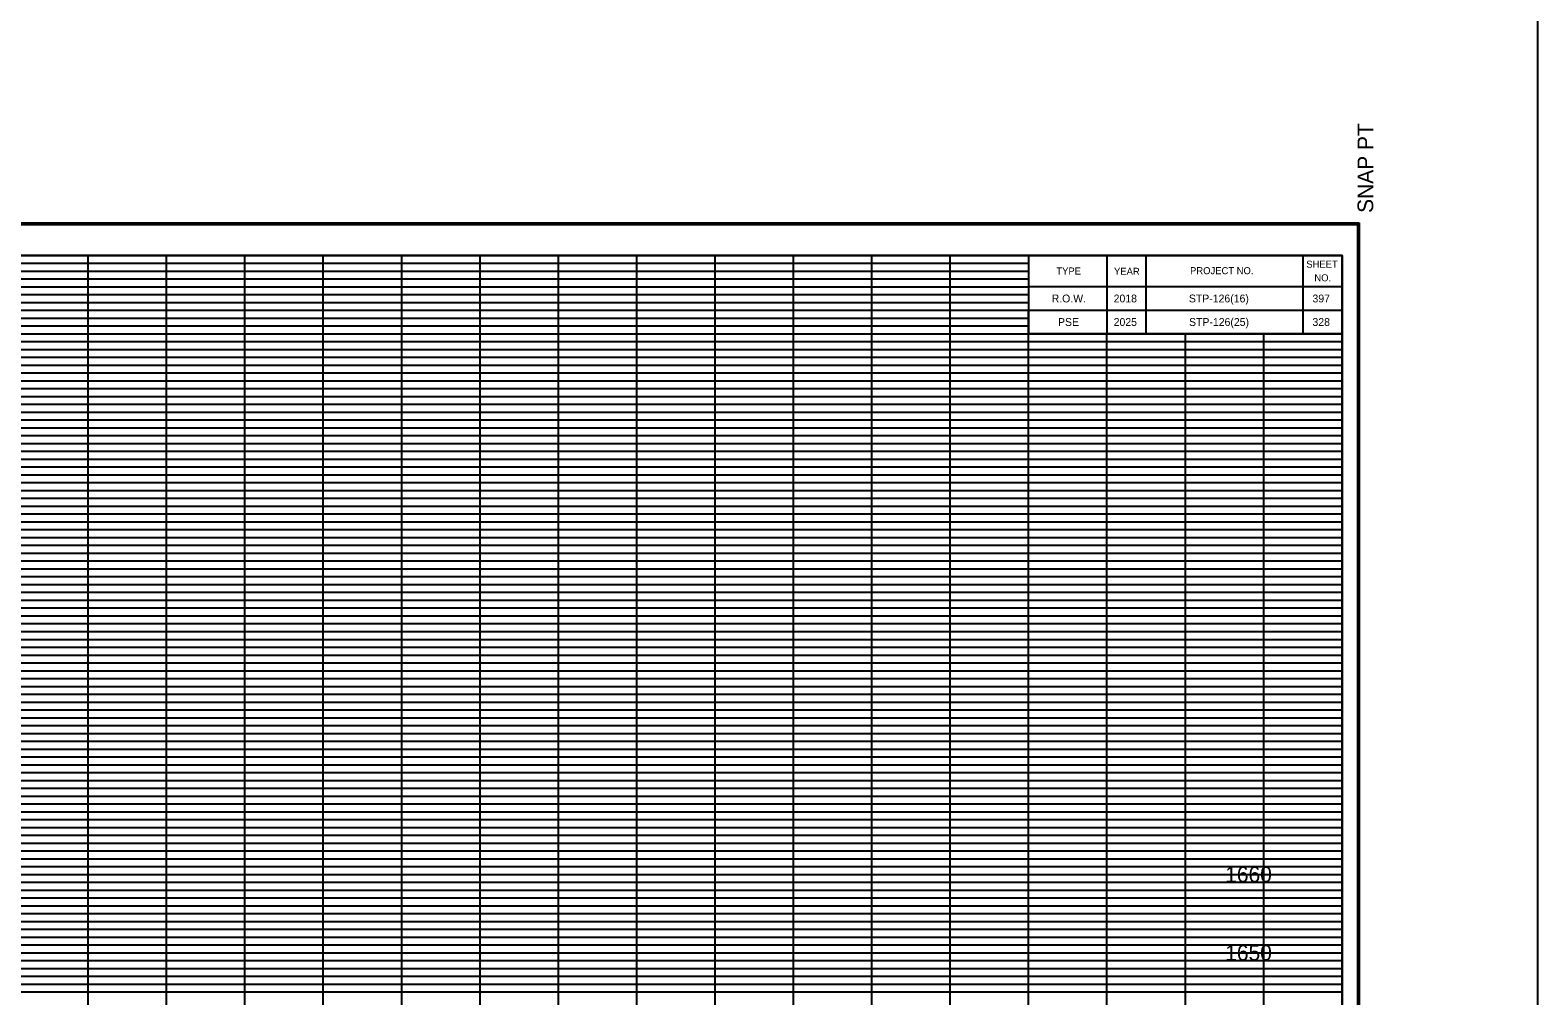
# Model space of a CAD drawing. Extents: x 955 to 1375, y 1248 to 3657.
# Drawn here: x 1152.6 to 1345, y 2735.5 to 2858.7 of the extents above; entities that cross this region are included whole.
import ezdxf

# ---------------------------------------------------------------- set-up
doc = ezdxf.new("R2010")
doc.units = 0
for name, color, linetype in [('DESIGN - SCRATCH - User 1', 7, 'Continuous'), ('DESIGN - SHEET - Corner Text', 7, 'Continuous'), ('DESIGN - SHEET - Light Grid', 7, 'Continuous'), ('DESIGN - SHEET - Linework', 7, 'Continuous'), ('DESIGN - SHEET - Plot Shape', 7, 'Continuous'), ('DESIGN - TYPICAL - Text', 7, 'Continuous'), ('DESIGN - UTILITIES - Cable (Overhead) with Text', 7, 'Continuous'), ('SURVEY - NON-TRANSPORTATION - Features Text', 7, 'Continuous')]:
    doc.layers.add(name, color=color, linetype=linetype)

# ---------------------------------------------------------------- blocks, each defined once
blk = doc.blocks.new('XSTSHT')
at = {"layer": 'DESIGN - SCRATCH - User 1'}
for p, q in [((28.5, 20.45), (28.5, 20.45)), ((29.24, 20.45), (29.24, 20.45)), ((30.49, 20.45), (30.49, 20.45)), ((31.74, 20.45), (31.74, 20.45)), ((28.5, 20.15), (28.5, 20.15)), ((29.24, 20.15), (29.24, 20.15)), ((30.49, 20.15), (30.49, 20.15)), ((31.74, 20.15), (31.74, 20.15))]:
    blk.add_line(p, q, dxfattribs=at)
at = {"layer": 'DESIGN - SHEET - Light Grid'}
for p, q in [((8, 20.9), (16, 20.9)), ((8, 20.8), (16, 20.8)), ((16, 20.9), (24, 20.9)), ((16, 20.8), (24, 20.8)), ((24, 20.9), (28, 20.9)), ((24, 20.8), (28, 20.8)), ((8, 20.7), (16, 20.7)), ((8, 20.6), (16, 20.6)), ((16, 20.7), (24, 20.7)), ((16, 20.6), (24, 20.6)), ((24, 20.7), (28, 20.7)), ((24, 20.6), (28, 20.6)), ((8, 20.5), (16, 20.5)), ((8, 20.4), (16, 20.4)), ((16, 20.5), (24, 20.5)), ((16, 20.4), (24, 20.4)), ((24, 20.5), (28, 20.5)), ((24, 20.4), (28, 20.4)), ((8, 20.3), (16, 20.3)), ((16, 20.3), (24, 20.3)), ((24, 20.3), (28, 20.3)), ((8, 20.2), (16, 20.2)), ((8, 20.1), (16, 20.1)), ((16, 20.2), (24, 20.2)), ((16, 20.1), (24, 20.1)), ((24, 20.2), (28, 20.2)), ((24, 20.1), (28, 20.1)), ((8, 19.9), (16, 19.9)), ((16, 19.9), (24, 19.9)), ((24, 19.9), (32, 19.9)), ((8, 19.8), (16, 19.8)), ((8, 19.7), (16, 19.7)), ((16, 19.8), (24, 19.8)), ((16, 19.7), (24, 19.7)), ((24, 19.8), (32, 19.8)), ((24, 19.7), (32, 19.7)), ((8, 19.6), (16, 19.6)), ((8, 19.5), (16, 19.5)), ((16, 19.6), (24, 19.6)), ((16, 19.5), (24, 19.5)), ((24, 19.6), (32, 19.6)), ((24, 19.5), (32, 19.5)), ((8, 19.4), (16, 19.4)), ((8, 19.3), (16, 19.3)), ((16, 19.4), (24, 19.4)), ((16, 19.3), (24, 19.3)), ((24, 19.4), (32, 19.4)), ((24, 19.3), (32, 19.3)), ((8, 19.2), (16, 19.2)), ((8, 19.1), (16, 19.1)), ((16, 19.2), (24, 19.2)), ((16, 19.1), (24, 19.1)), ((24, 19.2), (32, 19.2)), ((24, 19.1), (32, 19.1)), ((8, 18.9), (16, 18.9)), ((16, 18.9), (24, 18.9)), ((24, 18.9), (32, 18.9)), ((8, 18.8), (16, 18.8)), ((8, 18.7), (16, 18.7)), ((16, 18.8), (24, 18.8)), ((16, 18.7), (24, 18.7)), ((24, 18.8), (32, 18.8)), ((24, 18.7), (32, 18.7)), ((8, 18.6), (16, 18.6)), ((8, 18.5), (16, 18.5)), ((16, 18.6), (24, 18.6)), ((16, 18.5), (24, 18.5)), ((24, 18.6), (32, 18.6)), ((24, 18.5), (32, 18.5)), ((8, 18.4), (16, 18.4)), ((8, 18.3), (16, 18.3)), ((16, 18.4), (24, 18.4)), ((16, 18.3), (24, 18.3)), ((24, 18.4), (32, 18.4)), ((24, 18.3), (32, 18.3)), ((8, 18.2), (16, 18.2)), ((8, 18.1), (16, 18.1)), ((16, 18.2), (24, 18.2)), ((16, 18.1), (24, 18.1)), ((24, 18.2), (32, 18.2)), ((24, 18.1), (32, 18.1)), ((8, 17.9), (16, 17.9)), ((16, 17.9), (24, 17.9)), ((24, 17.9), (32, 17.9)), ((8, 17.8), (16, 17.8)), ((8, 17.7), (16, 17.7)), ((16, 17.8), (24, 17.8)), ((16, 17.7), (24, 17.7)), ((24, 17.8), (32, 17.8)), ((24, 17.7), (32, 17.7)), ((8, 17.6), (16, 17.6)), ((16, 17.6), (24, 17.6)), ((24, 17.6), (32, 17.6)), ((8, 17.5), (16, 17.5)), ((8, 17.4), (16, 17.4)), ((16, 17.5), (24, 17.5)), ((16, 17.4), (24, 17.4)), ((24, 17.5), (32, 17.5)), ((24, 17.4), (32, 17.4)), ((8, 17.3), (16, 17.3)), ((8, 17.2), (16, 17.2)), ((16, 17.3), (24, 17.3)), ((16, 17.2), (24, 17.2)), ((24, 17.3), (32, 17.3)), ((24, 17.2), (32, 17.2)), ((8, 17.1), (16, 17.1)), ((16, 17.1), (24, 17.1)), ((24, 17.1), (32, 17.1)), ((8, 16.9), (16, 16.9)), ((8, 16.8), (16, 16.8)), ((16, 16.9), (24, 16.9)), ((16, 16.8), (24, 16.8)), ((24, 16.9), (32, 16.9)), ((24, 16.8), (32, 16.8)), ((8, 16.7), (16, 16.7)), ((8, 16.6), (16, 16.6)), ((16, 16.7), (24, 16.7)), ((16, 16.6), (24, 16.6)), ((24, 16.7), (32, 16.7)), ((24, 16.6), (32, 16.6)), ((8, 16.5), (16, 16.5)), ((8, 16.4), (16, 16.4)), ((16, 16.5), (24, 16.5)), ((16, 16.4), (24, 16.4)), ((24, 16.5), (32, 16.5)), ((24, 16.4), (32, 16.4)), ((8, 16.3), (16, 16.3)), ((8, 16.2), (16, 16.2)), ((16, 16.3), (24, 16.3)), ((16, 16.2), (24, 16.2)), ((24, 16.3), (32, 16.3)), ((24, 16.2), (32, 16.2)), ((8, 16.1), (16, 16.1)), ((16, 16.1), (24, 16.1)), ((24, 16.1), (32, 16.1)), ((8, 15.9), (16, 15.9)), ((8, 15.8), (16, 15.8)), ((16, 15.9), (24, 15.9)), ((16, 15.8), (24, 15.8)), ((24, 15.9), (32, 15.9)), ((24, 15.8), (32, 15.8)), ((8, 15.7), (16, 15.7)), ((8, 15.6), (16, 15.6)), ((16, 15.7), (24, 15.7)), ((16, 15.6), (24, 15.6)), ((24, 15.7), (32, 15.7)), ((24, 15.6), (32, 15.6)), ((8, 15.5), (16, 15.5)), ((8, 15.4), (16, 15.4)), ((16, 15.5), (24, 15.5)), ((16, 15.4), (24, 15.4)), ((24, 15.5), (32, 15.5)), ((24, 15.4), (32, 15.4)), ((8, 15.3), (16, 15.3)), ((8, 15.2), (16, 15.2)), ((16, 15.3), (24, 15.3)), ((16, 15.2), (24, 15.2)), ((24, 15.3), (32, 15.3)), ((24, 15.2), (32, 15.2)), ((8, 15.1), (16, 15.1)), ((16, 15.1), (24, 15.1)), ((24, 15.1), (32, 15.1)), ((8, 14.9), (16, 14.9)), ((16, 14.9), (24, 14.9)), ((24, 14.9), (32, 14.9)), ((8, 14.8), (16, 14.8)), ((8, 14.7), (16, 14.7)), ((16, 14.8), (24, 14.8)), ((16, 14.7), (24, 14.7)), ((24, 14.8), (32, 14.8)), ((24, 14.7), (32, 14.7)), ((8, 14.6), (16, 14.6)), ((8, 14.5), (16, 14.5)), ((16, 14.6), (24, 14.6)), ((16, 14.5), (24, 14.5)), ((24, 14.6), (32, 14.6)), ((24, 14.5), (32, 14.5)), ((8, 14.4), (16, 14.4)), ((8, 14.3), (16, 14.3)), ((16, 14.4), (24, 14.4)), ((16, 14.3), (24, 14.3)), ((24, 14.4), (32, 14.4)), ((24, 14.3), (32, 14.3)), ((8, 14.2), (16, 14.2)), ((8, 14.1), (16, 14.1)), ((16, 14.2), (24, 14.2)), ((16, 14.1), (24, 14.1)), ((24, 14.2), (32, 14.2)), ((24, 14.1), (32, 14.1)), ((8, 13.9), (16, 13.9)), ((16, 13.9), (24, 13.9)), ((24, 13.9), (32, 13.9)), ((8, 13.8), (16, 13.8)), ((8, 13.7), (16, 13.7)), ((16, 13.8), (24, 13.8)), ((16, 13.7), (24, 13.7)), ((24, 13.8), (32, 13.8)), ((24, 13.7), (32, 13.7)), ((8, 13.6), (16, 13.6)), ((8, 13.5), (16, 13.5)), ((16, 13.6), (24, 13.6)), ((16, 13.5), (24, 13.5)), ((24, 13.6), (32, 13.6)), ((24, 13.5), (32, 13.5)), ((8, 13.4), (16, 13.4)), ((8, 13.3), (16, 13.3)), ((16, 13.4), (24, 13.4)), ((16, 13.3), (24, 13.3)), ((24, 13.4), (32, 13.4)), ((24, 13.3), (32, 13.3)), ((8, 13.2), (16, 13.2)), ((8, 13.1), (16, 13.1)), ((16, 13.2), (24, 13.2)), ((16, 13.1), (24, 13.1)), ((24, 13.2), (32, 13.2)), ((24, 13.1), (32, 13.1)), ((8, 12.9), (16, 12.9)), ((16, 12.9), (24, 12.9)), ((24, 12.9), (32, 12.9)), ((8, 12.8), (16, 12.8)), ((8, 12.7), (16, 12.7)), ((16, 12.8), (24, 12.8)), ((16, 12.7), (24, 12.7)), ((24, 12.8), (32, 12.8)), ((24, 12.7), (32, 12.7)), ((8, 12.6), (16, 12.6)), ((16, 12.6), (24, 12.6)), ((24, 12.6), (32, 12.6)), ((8, 12.5), (16, 12.5)), ((8, 12.4), (16, 12.4)), ((16, 12.5), (24, 12.5)), ((16, 12.4), (24, 12.4)), ((24, 12.5), (32, 12.5)), ((24, 12.4), (32, 12.4)), ((8, 12.3), (16, 12.3)), ((8, 12.2), (16, 12.2)), ((16, 12.3), (24, 12.3)), ((16, 12.2), (24, 12.2)), ((24, 12.3), (32, 12.3)), ((24, 12.2), (32, 12.2)), ((8, 12.1), (16, 12.1)), ((16, 12.1), (24, 12.1)), ((24, 12.1), (32, 12.1)), ((8, 11.9), (16, 11.9)), ((8, 11.8), (16, 11.8)), ((16, 11.9), (24, 11.9)), ((16, 11.8), (24, 11.8)), ((24, 11.9), (32, 11.9)), ((24, 11.8), (32, 11.8)), ((8, 11.7), (16, 11.7)), ((8, 11.6), (16, 11.6)), ((16, 11.7), (24, 11.7)), ((16, 11.6), (24, 11.6)), ((24, 11.7), (32, 11.7)), ((24, 11.6), (32, 11.6))]:
    blk.add_line(p, q, dxfattribs=at)
at = {"layer": 'DESIGN - SHEET - Linework'}
for p, q in [((-1.823, 21.414), (32.217, 21.414)), ((32.217, 21.414), (32.217, -0.414)), ((16, 0), (16, 21)), ((17, 0), (17, 21)), ((18, 0), (18, 21)), ((19, 0), (19, 21)), ((20, 0), (20, 21)), ((21, 0), (21, 21)), ((22, 0), (22, 21)), ((23, 0), (23, 21)), ((24, 0), (24, 21)), ((25, 0), (25, 21)), ((26, 0), (26, 21)), ((27, 0), (27, 21)), ((0, 20), (28, 20)), ((28, 0), (28, 20)), ((29, 0), (29, 20)), ((30, 0), (30, 20)), ((31, 0), (31, 20)), ((0, 19), (32, 19)), ((0, 18), (32, 18)), ((0, 17), (32, 17)), ((0, 16), (32, 16)), ((0, 15), (32, 15)), ((0, 14), (32, 14)), ((0, 13), (32, 13)), ((0, 12), (32, 12))]:
    blk.add_line(p, q, dxfattribs=at)
for points in [[(0, 21), (0, 0), (32, 0), (32, 21), (0, 21)], [(28, 21), (28, 20), (32, 20), (32, 21), (31.5, 21), (31.5, 20), (29.5, 20), (29.5, 21), (29, 21), (29, 20), (32, 20), (28, 20), (28, 20.3), (32, 20.3), (32, 20.6), (28, 20.6)]]:
    blk.add_lwpolyline(points, dxfattribs=at)
at = {"layer": 'DESIGN - SHEET - Plot Shape'}
for points in [[(-1.803, 21.394), (32.197, 21.394), (32.197, -0.394), (-1.803, -0.394)], [(-0.85, 21), (32, 21), (32, -0.25), (-0.85, -0.25)]]:
    blk.add_lwpolyline(points, close=True, dxfattribs=at)
at = {"layer": 'DESIGN - SHEET - Corner Text'}
blk.add_text('  SNAP PT', height=0.2, rotation=90, dxfattribs=at).set_placement((32.397, 21.394))
for s, p in [('TYPE', (28.354, 20.756)), ('YEAR', (29.09, 20.752)), ('PROJECT NO.', (30.06, 20.76)), ('SHEET', (31.543, 20.843)), ('NO.', (31.646, 20.669))]:
    blk.add_text(s, height=0.09, dxfattribs=at).set_placement(p)

msp = doc.modelspace()

# ---------------------------------------------------------------- linework, layer by layer
at = {"layer": 'DESIGN - SHEET - Plot Shape'}
msp.add_lwpolyline([(991.5, 2617.5), (1320, 2617.5), (1320, 2830), (991.5, 2830)], close=True, dxfattribs=at)
at = {"layer": 'SURVEY - NON-TRANSPORTATION - Features Text'}
msp.add_lwpolyline([(955.41, 1505.76), (1344.98, 1505.76), (1344.98, 3398.01), (955.41, 3398.01)], close=True, dxfattribs=at)

# ---------------------------------------------------------------- block references
at = {"layer": 'DESIGN - UTILITIES - Cable (Overhead) with Text', "xscale": 10, "yscale": 10}
msp.add_blockref('XSTSHT', (1000, 2620), dxfattribs=at)

# ---------------------------------------------------------------- texts
at = {"layer": 'DESIGN - SHEET - Corner Text'}
for s, p in [('R.O.W.', (1282.94, 2824)), ('2018', (1290.85, 2824)), ('STP-126(16)', (1300.45, 2824)), ('397', (1316.22, 2824)), ('PSE', (1283.75, 2821)), ('2025', (1290.85, 2821)), ('STP-126(25)', (1300.47, 2821)), ('328', (1316.22, 2821))]:
    msp.add_text(s, height=1, dxfattribs=at).set_placement(p)
at = {"layer": 'DESIGN - TYPICAL - Text'}
for s, p in [('     1660     ', (1301.37, 2750)), ('     1650     ', (1301.37, 2740))]:
    msp.add_text(s, height=2, dxfattribs=at).set_placement(p)

doc.saveas('drawing.dxf')
